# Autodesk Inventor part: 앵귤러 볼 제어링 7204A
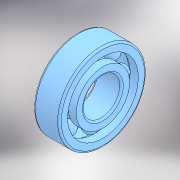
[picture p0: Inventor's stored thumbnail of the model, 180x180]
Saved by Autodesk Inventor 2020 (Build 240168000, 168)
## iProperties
Created: 2024-11
Part Number: 앵귤러 볼 제어링 7204A
Material: 강철, 연강
Description: 앵귤러 콘택트 볼 베어링
Document SubType Name: Modeling
Designer: 1강의실14
Density: 7.85 g/cm^3
Appearance: 기본값
Author: jhkim
Sending System: Autodesk Inventor 2025
Preprocessor: ST-DEVELOPER v20
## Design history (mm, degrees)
feature "Solid1"
feature "Solid1:1"
feature "Solid1:2"
feature "Solid1:3"
feature "Solid1:4"
feature "Solid1:5"
feature "Solid1:6"
feature "Solid1:7"
feature "Solid1:8"
feature "Solid1:9"
node "솔리드1"
node "솔리드2"
node "솔리드3"
node "솔리드4"
node "솔리드5"
node "솔리드6"
node "솔리드7"
node "솔리드8"
node "솔리드9"
node "솔리드10"
